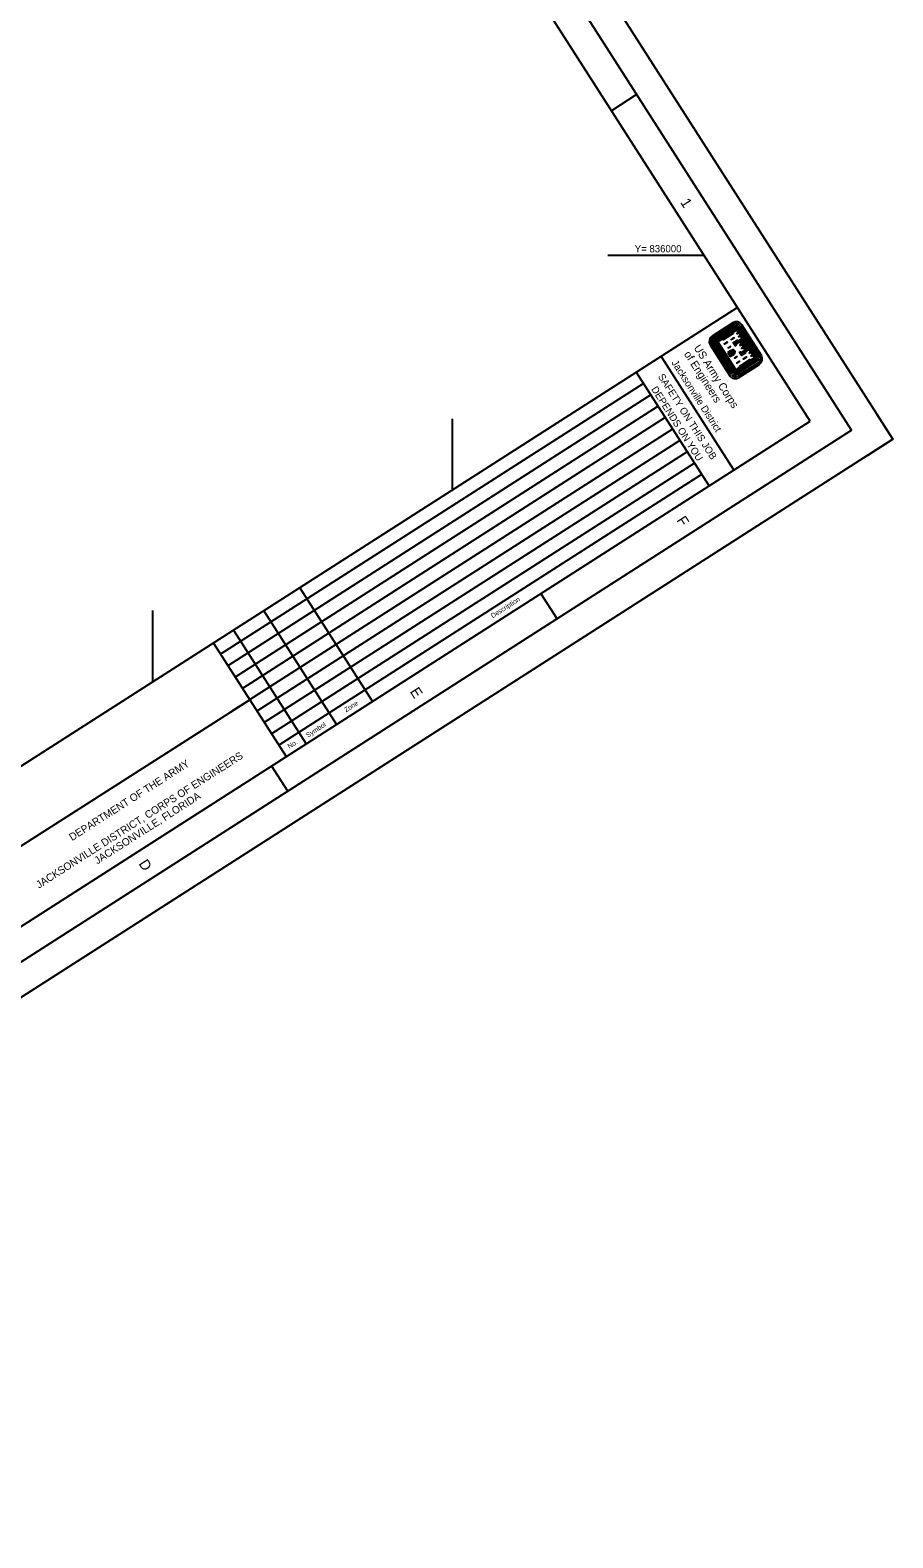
# Model space of a CAD drawing. Extents: x 584499 to 589735, y 833860 to 839399.
# Drawn here: x 588295 to 589735, y 833860 to 836376 of the extents above; entities that cross this region are included whole.
import ezdxf

# ---------------------------------------------------------------- set-up
doc = ezdxf.new("R2010")
doc.units = 0
for name, color, linetype in [('G-ANNO-NPLT', 7, 'Continuous'), ('G-ANNO-TEXT-LOGO', 7, 'Continuous'), ('G-ANNO-TEXT-TTLB', 7, 'Continuous'), ('G-ANNO-TTLB', 7, 'Continuous'), ('V-TOPO-COOR-STAT', 7, 'Continuous')]:
    doc.layers.add(name, color=color, linetype=linetype)

msp = doc.modelspace()

# ---------------------------------------------------------------- linework, layer by layer
at = {"layer": 'G-ANNO-NPLT'}
msp.add_lwpolyline([(587362.9, 839398.7), (589735, 835692.9), (586871.4, 833859.9), (584499.3, 837565.7)], close=True, dxfattribs=at)
msp.add_lwpolyline([(589692.9, 835666), (589735, 835692.9), (589708, 835735)], dxfattribs=at)
at = {"layer": 'G-ANNO-TEXT-LOGO'}
for p, q in [((589468, 835887.3), (589433.4, 835865.2)), ((589435.2, 835862.5), (589469.7, 835884.6)), ((589471.6, 835881.6), (589437.1, 835859.5)), ((589472.1, 835880.9), (589437.5, 835858.8)), ((589472.5, 835880.2), (589438, 835858.1)), ((589473, 835879.4), (589438.5, 835857.3)), ((589473.5, 835878.7), (589438.9, 835856.6)), ((589474, 835877.9), (589439.7, 835856)), ((589474.4, 835877.3), (589440.9, 835855.8)), ((589467.4, 835872), (589449.8, 835860.7)), ((589467.2, 835870.7), (589451.1, 835860.4)), ((589507, 835827.4), (589474.2, 835878.6)), ((589507.8, 835827.9), (589475, 835879.1)), ((589508.5, 835828.3), (589475.7, 835879.5)), ((589509.2, 835828.8), (589476.4, 835880)), ((589510, 835829.3), (589477.2, 835880.5)), ((589480.1, 835882.3), (589512.8, 835831.1)), ((589515.5, 835832.8), (589482.8, 835884)), ((589430.1, 835850.3), (589462.9, 835799.1)), ((589465.7, 835800.9), (589432.9, 835852.1)), ((589468.6, 835802.8), (589435.8, 835854)), ((589469.3, 835803.2), (589436.5, 835854.4)), ((589470.1, 835803.7), (589437.3, 835854.9)), ((589470.8, 835804.2), (589438, 835855.4)), ((589471.5, 835804.6), (589438.7, 835855.8)), ((589472, 835805.4), (589439.7, 835856)), ((589472.4, 835806.6), (589440.9, 835855.8)), ((589459.4, 835837.8), (589465.1, 835841.4)), ((589459.4, 835837.8), (589463.7, 835831)), ((589459.9, 835837.1), (589465.5, 835840.7)), ((589460.3, 835836.3), (589466, 835839.9)), ((589460.8, 835835.6), (589466.5, 835839.2)), ((589461.3, 835834.9), (589466.9, 835838.5)), ((589461.9, 835833.9), (589467.5, 835837.5)), ((589462.3, 835833.2), (589468, 835836.8)), ((589462.8, 835832.4), (589468.5, 835836.1)), ((589480.6, 835857.6), (589490.6, 835841.9)), ((589481.3, 835858.1), (589491.4, 835842.4)), ((589482, 835858.5), (589492, 835842.8)), ((589482.8, 835859), (589492.8, 835843.3)), ((589483.5, 835859.5), (589493.5, 835843.8)), ((589484.2, 835859.9), (589494.2, 835844.2)), ((589484.9, 835860.4), (589495, 835844.7)), ((589463.3, 835831.7), (589468.9, 835835.3)), ((589463.7, 835831), (589469.4, 835834.6)), ((589506.3, 835827.4), (589472, 835805.4)), ((589506.8, 835826.6), (589472.3, 835804.5)), ((589505.9, 835828.1), (589472.4, 835806.6)), ((589507.3, 835825.9), (589472.7, 835803.8)), ((589507.7, 835825.2), (589473.2, 835803.1)), ((589508.2, 835824.4), (589473.7, 835802.3)), ((589508.7, 835823.7), (589474.1, 835801.6)), ((589510.5, 835820.8), (589476, 835798.7)), ((589477.8, 835795.9), (589512.3, 835818)), ((589498.1, 835823.9), (589480.6, 835812.7)), ((589496.9, 835824.2), (589480.8, 835813.9))]:
    msp.add_line(p, q, dxfattribs=at)
for points in [[(589474.8, 835876.7), (589468.1, 835872.4), (589467.6, 835870.1), (589451.5, 835859.8), (589449.1, 835860.2), (589441.8, 835855.5), (589472.5, 835807.5), (589479.8, 835812.2), (589480.4, 835814.7), (589496.4, 835825), (589498.8, 835824.4), (589505.5, 835828.7), (589501.5, 835835), (589498.3, 835839.9), (589495.4, 835844.4), (589488.8, 835840.1), (589488.4, 835837.6), (589482.5, 835833.9), (589480.2, 835837.4), (589480.8, 835837.8), (589483.3, 835837.2), (589489.8, 835841.4), (589485.8, 835847.7), (589482.7, 835852.6), (589479.8, 835857.1), (589473.2, 835852.9), (589472.7, 835850.4), (589472.1, 835850), (589469.8, 835853.6), (589475.7, 835857.3), (589478.1, 835856.7), (589484.8, 835861), (589480.8, 835867.3), (589477.6, 835872.2), (589474.8, 835876.7)], [(589474.4, 835875.5), (589468.9, 835871.9), (589468.3, 835869.5), (589451.7, 835858.8), (589449.2, 835859.3), (589442.9, 835855.3), (589472.8, 835808.7), (589479, 835812.7), (589479.5, 835815.2), (589496.2, 835825.9), (589498.7, 835825.3), (589504.3, 835828.8), (589501.4, 835833.4), (589498.8, 835831.7), (589498.5, 835832.1), (589501.1, 835833.8), (589498.3, 835838.3), (589495.7, 835836.6), (589495.4, 835836.9), (589498.1, 835838.6), (589495.1, 835843.2), (589489.6, 835839.6), (589489, 835837.1), (589482.2, 835832.7), (589479.1, 835837.6), (589480.7, 835838.7), (589483.2, 835838.1), (589488.7, 835841.7), (589485.8, 835846.2), (589483.2, 835844.5), (589483, 835844.9), (589485.6, 835846.6), (589482.7, 835851.1), (589480.1, 835849.4), (589479.8, 835849.9), (589482.4, 835851.5), (589479.6, 835856), (589474, 835852.4), (589473.5, 835849.9), (589471.9, 835848.9), (589468.7, 835853.8), (589475.6, 835858.2), (589478, 835857.6), (589483.6, 835861.2), (589480.7, 835865.6), (589478.1, 835864), (589477.9, 835864.4), (589480.5, 835866.1), (589477.6, 835870.6), (589475, 835868.9), (589474.7, 835869.3), (589477.4, 835871), (589474.4, 835875.5)], [(589469.8, 835862.8), (589465, 835859.7), (589465.3, 835859.2), (589470.2, 835862.3), (589469.8, 835862.8)], [(589458.6, 835855.7), (589453.7, 835852.5), (589454, 835852), (589459, 835855.2), (589458.6, 835855.7)], [(589463.6, 835847.9), (589460.2, 835845.7), (589460.4, 835845.3), (589463.9, 835847.5), (589463.6, 835847.9)], [(589476.6, 835856.2), (589475.9, 835856.4), (589471.1, 835853.3), (589472.1, 835851.7), (589472.5, 835853.5), (589476.7, 835856.2)], [(589487.7, 835838.9), (589487.5, 835838.2), (589482.7, 835835.1), (589481.8, 835836.6), (589483.5, 835836.3), (589487.7, 835839)], [(589474.7, 835830.6), (589471.3, 835828.3), (589471, 835828.8), (589474.4, 835831), (589474.7, 835830.6)], [(589479.6, 835822.9), (589474.6, 835819.7), (589474.4, 835820.1), (589479.3, 835823.3), (589479.6, 835822.9)], [(589490.8, 835830.1), (589485.9, 835826.9), (589485.7, 835827.4), (589490.5, 835830.5), (589490.8, 835830.1)]]:
    msp.add_lwpolyline(points, dxfattribs=at)
for centre, major_axis, start_param, end_param in [((589473.8, 835878.2), (5.78, -9.02), 1.57078, 3.141576), ((589473.8, 835878.2), (4.04, -6.31), 1.57078, 3.141576), ((589439.2, 835856.1), (-5.78, 9.02), 6.28317, 7.853966), ((589439.2, 835856.1), (-4.04, 6.31), 6.28317, 7.853966), ((589473.8, 835878.2), (2.17, -3.38), 1.57078, 3.141576), ((589473.8, 835878.2), (1.7, -2.65), 1.57078, 3.141576), ((589473.8, 835878.2), (1.23, -1.92), 1.57078, 3.141576), ((589473.8, 835878.2), (0.76, -1.19), 1.57078, 3.141576), ((589473.8, 835878.2), (0.294, -0.46), 1.57078, 3.141576), ((589439.2, 835856.1), (-2.17, 3.38), 6.28317, 7.853966), ((589439.2, 835856.1), (-1.7, 2.65), 6.28317, 7.853966), ((589439.2, 835856.1), (-1.23, 1.92), 6.28317, 7.853966), ((589439.2, 835856.1), (-0.76, 1.19), 6.28317, 7.853966), ((589439.2, 835856.1), (-0.294, 0.46), 6.28317, 7.853966), ((589467.6, 835836.5), (-2.99, 4.68), 4.985832, 6.214359), ((589467.6, 835836.5), (-2.53, 3.95), 4.947465, 6.21436), ((589467.6, 835836.5), (-2.06, 3.22), 4.947465, 6.21436), ((589467.6, 835836.5), (-1.59, 2.48), 4.947465, 6.21436), ((589467.6, 835836.5), (-1.12, 1.75), 4.947465, 6.214359), ((589466, 835839), (1.12, -1.75), 0.068794, 1.335689), ((589466, 835839), (1.59, -2.48), 0.068794, 1.335689), ((589466, 835839), (2.06, -3.22), 0.068795, 1.335689), ((589466, 835839), (2.53, -3.95), 0.068795, 1.335689), ((589466, 835839), (2.99, -4.68), 0.068795, 1.29842), ((589506.5, 835827.1), (0.294, -0.46), 6.283169, 7.853965), ((589506.5, 835827.1), (0.76, -1.19), 6.283169, 7.853965), ((589506.5, 835827.1), (1.23, -1.92), 6.283169, 7.853965), ((589506.5, 835827.1), (1.7, -2.65), 6.283169, 7.853965), ((589506.5, 835827.1), (2.17, -3.38), 6.283169, 7.853965), ((589506.5, 835827.1), (4.04, -6.31), 6.28317, 7.853966), ((589506.5, 835827.1), (5.78, -9.02), 6.283169, 7.853965), ((589471.9, 835805), (5.78, -9.02), 4.712373, 6.28317), ((589471.9, 835805), (-4.04, 6.31), 1.570781, 3.141577), ((589471.9, 835805), (2.17, -3.38), 4.712373, 6.28317), ((589471.9, 835805), (1.7, -2.65), 4.712373, 6.28317), ((589471.9, 835805), (1.23, -1.92), 4.712373, 6.28317), ((589471.9, 835805), (0.76, -1.19), 4.712373, 6.28317), ((589471.9, 835805), (0.294, -0.46), 4.712373, 6.28317)]:
    msp.add_ellipse(centre, major_axis=major_axis, ratio=0.99964, start_param=start_param, end_param=end_param, dxfattribs=at)
at = {"layer": 'G-ANNO-TTLB'}
for p, q in [((589307.4, 836268.1), (589265.3, 836241.2)), ((589475.5, 835912.7), (586780.4, 834187.6)), ((589348.2, 835831.2), (589469.5, 835641.7)), ((589318.8, 835785.9), (588613.1, 835334.2)), ((589306.5, 835805.2), (589427.8, 835615.7)), ((589330.9, 835767), (588625.2, 835315.2)), ((589343.1, 835748), (588637.4, 835296.3)), ((589355.2, 835729.1), (588649.5, 835277.3)), ((589367.3, 835710.1), (588661.6, 835258.4)), ((589379.5, 835691.2), (588673.7, 835239.4)), ((589391.6, 835672.2), (588685.9, 835220.5)), ((589403.7, 835653.3), (588698, 835201.5)), ((589415.9, 835634.3), (588710.1, 835182.6)), ((588745.1, 835445.2), (588866.4, 835255.7)), ((589174.5, 835393.5), (589147.5, 835435.6)), ((588685.2, 835406.8), (588806.5, 835217.3)), ((588634.6, 835374.5), (588755.9, 835184.9)), ((588601.1, 835353), (588722.4, 835163.5)), ((587937.4, 834795.4), (588661.7, 835258.2)), ((588661.7, 835258.2), (588631.9, 835239.2)), ((588725.3, 835106), (588698.3, 835148.1))]:
    msp.add_line(p, q, dxfattribs=at)
for points in [[(584568.4, 837550.6), (586886.5, 833929), (589665.9, 835708.1), (587347.7, 839329.7)], [(589596.8, 835723.2), (587373, 839197.4), (584677.9, 837472.3), (586901.7, 833998.1)]]:
    msp.add_lwpolyline(points, close=True, dxfattribs=at)
at = {"layer": 'V-TOPO-COOR-STAT'}
for p, q in [((589259.4, 836000), (589419.7, 836000)), ((589000, 835608.4), (589000, 835727.1)), ((588500, 835288.3), (588500, 835407.1))]:
    msp.add_line(p, q, dxfattribs=at)

# ---------------------------------------------------------------- texts
at = {"layer": 'G-ANNO-TEXT-TTLB'}
for s, height, rotation, p in [('of Engineers', 13.086, 302.6232, (589385.8, 835835.2)), ('US Army Corps', 13.086, 302.6232, (589402.1, 835845.6)), ('Jacksonville District', 11.9, 302.6232, (589365, 835820.7)), ('SAFETY ON THIS JOB', 11.9, 302.6232, (589342.4, 835797.7)), ('DEPENDS ON YOU', 11.9, 302.6232, (589331.2, 835776.6)), ('Description', 8, 32.6232, (589067.2, 835394.1)), ('Zone', 8, 32.6232, (588822.5, 835237.2)), ('Symbol', 8, 32.6232, (588758.8, 835195)), ('No.', 8, 32.6232, (588727.9, 835176.4)), ('JACKSONVILLE DISTRICT, CORPS OF ENGINEERS', 12.5, 32.6232, (588310, 834943)), ('DEPARTMENT OF THE ARMY', 12.5, 32.6232, (588365.3, 835022.4)), ('JACKSONVILLE, FLORIDA', 12.5, 32.6232, (588407.4, 834983.4))]:
    msp.add_text(s, height=height, rotation=rotation, dxfattribs=at).set_placement(p)
at = {"layer": 'G-ANNO-TTLB'}
for s, p in [('1', (589379.6, 836088.3)), ('F', (589373.4, 835557.9)), ('E', (588928.4, 835272.1)), ('D', (588475.7, 834985))]:
    msp.add_text(s, height=17.5, rotation=302.6232, dxfattribs=at).set_placement(p)
at = {"layer": 'V-TOPO-COOR-STAT'}
msp.add_text('Y= 836000', height=12, dxfattribs=at).set_placement((589304.2, 836005))

doc.saveas('drawing.dxf')
